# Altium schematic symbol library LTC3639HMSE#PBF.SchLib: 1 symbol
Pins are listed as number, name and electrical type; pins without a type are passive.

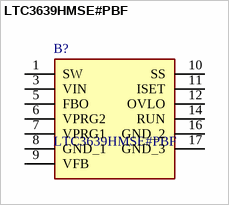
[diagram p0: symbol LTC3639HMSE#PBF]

## LTC3639HMSE#PBF
designator B?
High Efficiency, 150V 100mA Synchronous Step-Down Regulator; Manufacturer_Name: Analog Devices; Geometry.Height: 1.1mm
footprint LTC3639HMSEPBF
pins: 1 SW, 3 VIN, 5 FBO, 6 VPRG2, 7 VPRG1, 8 GND_1, 9 VFB, 10 SS, 11 ISET, 12 OVLO, 14 RUN, 16 GND_2, 17 GND_3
